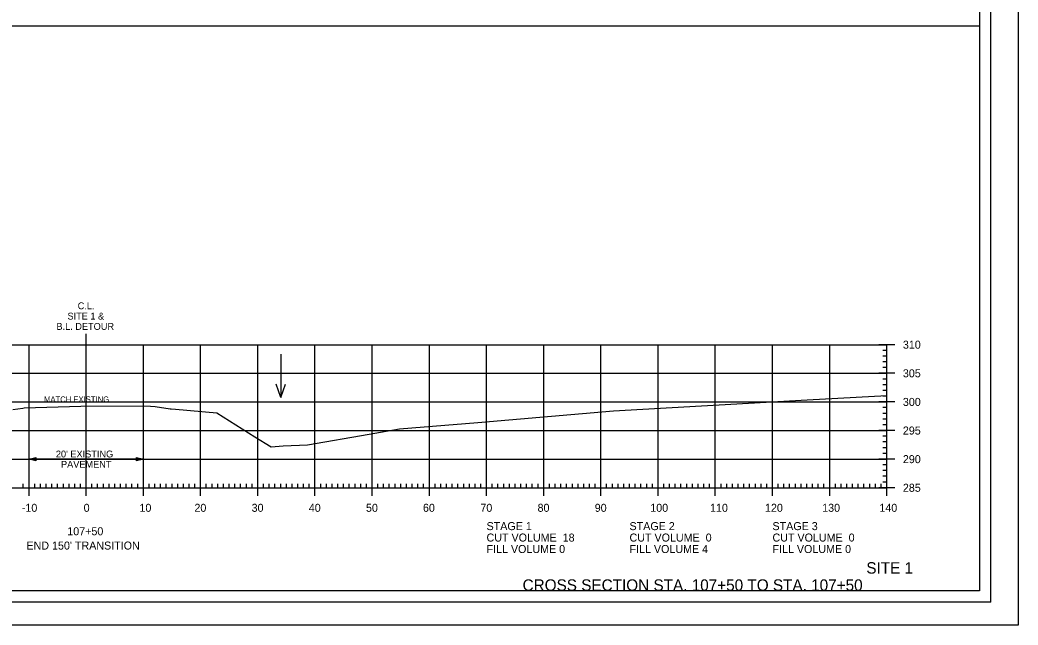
# Model space of a CAD drawing. Extents: x 1368713 to 1370673, y 380279 to 380950.
# Drawn here: x 1370140.7 to 1370315.2, y 380737.1 to 380842.8 of the extents above; entities that cross this region are included whole.
import ezdxf

# ---------------------------------------------------------------- set-up
doc = ezdxf.new("R2010")
doc.units = 0
for name, color, linetype in [('R_Axis', 7, 'Continuous'), ('R_Axis Annot', 7, 'Continuous'), ('R_Border', 7, 'Continuous'), ('R_Draft', 7, 'Continuous'), ('R_Exist Surface', 7, 'Continuous'), ('R_Grid', 7, 'Continuous'), ('R_No Plot', 7, 'Continuous'), ('R_ROW Annot', 7, 'Continuous'), ('R_Water Annot', 7, 'Continuous'), ('R_Xsect Slope', 7, 'Continuous')]:
    doc.layers.add(name, color=color, linetype=linetype)

msp = doc.modelspace()

# ---------------------------------------------------------------- linework, layer by layer
at = {"layer": 'R_Axis'}
for p, q in [((1370293.68, 380786.09), (1370290.88, 380786.09)), ((1370292.28, 380785.09), (1370291.58, 380785.09)), ((1370292.28, 380761.09), (1370292.28, 380786.09)), ((1370292.28, 380784.09), (1370291.58, 380784.09)), ((1370292.28, 380783.09), (1370291.58, 380783.09)), ((1370293.68, 380781.09), (1370290.88, 380781.09)), ((1370292.28, 380782.09), (1370291.58, 380782.09)), ((1370292.28, 380780.09), (1370291.58, 380780.09)), ((1370292.28, 380779.09), (1370291.58, 380779.09)), ((1370292.28, 380778.09), (1370291.58, 380778.09)), ((1370293.68, 380776.09), (1370290.88, 380776.09)), ((1370292.28, 380777.09), (1370291.58, 380777.09)), ((1370292.28, 380775.09), (1370291.58, 380775.09)), ((1370292.28, 380774.09), (1370291.58, 380774.09)), ((1370292.28, 380773.09), (1370291.58, 380773.09)), ((1370293.68, 380771.09), (1370290.88, 380771.09)), ((1370292.28, 380772.09), (1370291.58, 380772.09)), ((1370292.28, 380770.09), (1370291.58, 380770.09)), ((1370292.28, 380769.09), (1370291.58, 380769.09)), ((1370292.28, 380768.09), (1370291.58, 380768.09)), ((1370292.28, 380767.09), (1370291.58, 380767.09)), ((1370293.68, 380766.09), (1370290.88, 380766.09)), ((1370292.28, 380765.09), (1370291.58, 380765.09)), ((1370292.28, 380764.09), (1370291.58, 380764.09)), ((1370141.28, 380761.09), (1370141.28, 380761.79)), ((1370142.28, 380759.69), (1370142.28, 380762.49)), ((1370143.28, 380761.09), (1370143.28, 380761.79)), ((1370144.28, 380761.09), (1370144.28, 380761.79)), ((1370145.28, 380761.09), (1370145.28, 380761.79)), ((1370146.28, 380761.09), (1370146.28, 380761.79)), ((1370147.28, 380761.09), (1370147.28, 380761.79)), ((1370148.28, 380761.09), (1370148.28, 380761.79)), ((1370149.28, 380761.09), (1370149.28, 380761.79)), ((1370150.28, 380761.09), (1370150.28, 380761.79)), ((1370151.28, 380761.09), (1370151.28, 380761.79)), ((1370152.28, 380759.69), (1370152.28, 380762.49)), ((1370153.28, 380761.09), (1370153.28, 380761.79)), ((1370154.28, 380761.09), (1370154.28, 380761.79)), ((1370155.28, 380761.09), (1370155.28, 380761.79)), ((1370156.28, 380761.09), (1370156.28, 380761.79)), ((1370157.28, 380761.09), (1370157.28, 380761.79)), ((1370158.28, 380761.09), (1370158.28, 380761.79)), ((1370159.28, 380761.09), (1370159.28, 380761.79)), ((1370160.28, 380761.09), (1370160.28, 380761.79)), ((1370161.28, 380761.09), (1370161.28, 380761.79)), ((1370162.28, 380759.69), (1370162.28, 380762.49)), ((1370163.28, 380761.09), (1370163.28, 380761.79)), ((1370164.28, 380761.09), (1370164.28, 380761.79)), ((1370165.28, 380761.09), (1370165.28, 380761.79)), ((1370166.28, 380761.09), (1370166.28, 380761.79)), ((1370167.28, 380761.09), (1370167.28, 380761.79)), ((1370168.28, 380761.09), (1370168.28, 380761.79)), ((1370169.28, 380761.09), (1370169.28, 380761.79)), ((1370170.28, 380761.09), (1370170.28, 380761.79)), ((1370171.28, 380761.09), (1370171.28, 380761.79)), ((1370172.28, 380759.69), (1370172.28, 380762.49)), ((1370173.28, 380761.09), (1370173.28, 380761.79)), ((1370174.28, 380761.09), (1370174.28, 380761.79)), ((1370175.28, 380761.09), (1370175.28, 380761.79)), ((1370176.28, 380761.09), (1370176.28, 380761.79)), ((1370177.28, 380761.09), (1370177.28, 380761.79)), ((1370178.28, 380761.09), (1370178.28, 380761.79)), ((1370179.28, 380761.09), (1370179.28, 380761.79)), ((1370180.28, 380761.09), (1370180.28, 380761.79)), ((1370181.28, 380761.09), (1370181.28, 380761.79)), ((1370182.28, 380759.69), (1370182.28, 380762.49)), ((1370183.28, 380761.09), (1370183.28, 380761.79)), ((1370184.28, 380761.09), (1370184.28, 380761.79)), ((1370185.28, 380761.09), (1370185.28, 380761.79)), ((1370186.28, 380761.09), (1370186.28, 380761.79)), ((1370187.28, 380761.09), (1370187.28, 380761.79)), ((1370188.28, 380761.09), (1370188.28, 380761.79)), ((1370189.28, 380761.09), (1370189.28, 380761.79)), ((1370190.28, 380761.09), (1370190.28, 380761.79)), ((1370191.28, 380761.09), (1370191.28, 380761.79)), ((1370192.28, 380759.69), (1370192.28, 380762.49)), ((1370193.28, 380761.09), (1370193.28, 380761.79)), ((1370194.28, 380761.09), (1370194.28, 380761.79)), ((1370195.28, 380761.09), (1370195.28, 380761.79)), ((1370196.28, 380761.09), (1370196.28, 380761.79)), ((1370197.28, 380761.09), (1370197.28, 380761.79)), ((1370198.28, 380761.09), (1370198.28, 380761.79)), ((1370199.28, 380761.09), (1370199.28, 380761.79)), ((1370200.28, 380761.09), (1370200.28, 380761.79)), ((1370201.28, 380761.09), (1370201.28, 380761.79)), ((1370202.28, 380759.69), (1370202.28, 380762.49)), ((1370203.28, 380761.09), (1370203.28, 380761.79)), ((1370204.28, 380761.09), (1370204.28, 380761.79)), ((1370205.28, 380761.09), (1370205.28, 380761.79)), ((1370206.28, 380761.09), (1370206.28, 380761.79)), ((1370207.28, 380761.09), (1370207.28, 380761.79)), ((1370208.28, 380761.09), (1370208.28, 380761.79)), ((1370209.28, 380761.09), (1370209.28, 380761.79)), ((1370210.28, 380761.09), (1370210.28, 380761.79)), ((1370211.28, 380761.09), (1370211.28, 380761.79)), ((1370212.28, 380759.69), (1370212.28, 380762.49)), ((1370213.28, 380761.09), (1370213.28, 380761.79)), ((1370214.28, 380761.09), (1370214.28, 380761.79)), ((1370215.28, 380761.09), (1370215.28, 380761.79)), ((1370216.28, 380761.09), (1370216.28, 380761.79)), ((1370217.28, 380761.09), (1370217.28, 380761.79)), ((1370218.28, 380761.09), (1370218.28, 380761.79)), ((1370219.28, 380761.09), (1370219.28, 380761.79)), ((1370220.28, 380761.09), (1370220.28, 380761.79)), ((1370221.28, 380761.09), (1370221.28, 380761.79)), ((1370222.28, 380759.69), (1370222.28, 380762.49)), ((1370223.28, 380761.09), (1370223.28, 380761.79)), ((1370224.28, 380761.09), (1370224.28, 380761.79)), ((1370225.28, 380761.09), (1370225.28, 380761.79)), ((1370226.28, 380761.09), (1370226.28, 380761.79)), ((1370227.28, 380761.09), (1370227.28, 380761.79)), ((1370228.28, 380761.09), (1370228.28, 380761.79)), ((1370229.28, 380761.09), (1370229.28, 380761.79)), ((1370230.28, 380761.09), (1370230.28, 380761.79)), ((1370231.28, 380761.09), (1370231.28, 380761.79)), ((1370232.28, 380759.69), (1370232.28, 380762.49)), ((1370233.28, 380761.09), (1370233.28, 380761.79)), ((1370234.28, 380761.09), (1370234.28, 380761.79)), ((1370235.28, 380761.09), (1370235.28, 380761.79)), ((1370236.28, 380761.09), (1370236.28, 380761.79)), ((1370237.28, 380761.09), (1370237.28, 380761.79)), ((1370238.28, 380761.09), (1370238.28, 380761.79)), ((1370239.28, 380761.09), (1370239.28, 380761.79)), ((1370240.28, 380761.09), (1370240.28, 380761.79)), ((1370241.28, 380761.09), (1370241.28, 380761.79)), ((1370242.28, 380759.69), (1370242.28, 380762.49)), ((1370243.28, 380761.09), (1370243.28, 380761.79)), ((1370244.28, 380761.09), (1370244.28, 380761.79)), ((1370245.28, 380761.09), (1370245.28, 380761.79)), ((1370246.28, 380761.09), (1370246.28, 380761.79)), ((1370247.28, 380761.09), (1370247.28, 380761.79)), ((1370248.28, 380761.09), (1370248.28, 380761.79)), ((1370249.28, 380761.09), (1370249.28, 380761.79)), ((1370250.28, 380761.09), (1370250.28, 380761.79)), ((1370251.28, 380761.09), (1370251.28, 380761.79)), ((1370252.28, 380759.69), (1370252.28, 380762.49)), ((1370253.28, 380761.09), (1370253.28, 380761.79)), ((1370254.28, 380761.09), (1370254.28, 380761.79)), ((1370255.28, 380761.09), (1370255.28, 380761.79)), ((1370256.28, 380761.09), (1370256.28, 380761.79)), ((1370257.28, 380761.09), (1370257.28, 380761.79)), ((1370258.28, 380761.09), (1370258.28, 380761.79)), ((1370259.28, 380761.09), (1370259.28, 380761.79)), ((1370260.28, 380761.09), (1370260.28, 380761.79)), ((1370261.28, 380761.09), (1370261.28, 380761.79)), ((1370262.28, 380759.69), (1370262.28, 380762.49)), ((1370263.28, 380761.09), (1370263.28, 380761.79)), ((1370264.28, 380761.09), (1370264.28, 380761.79)), ((1370265.28, 380761.09), (1370265.28, 380761.79)), ((1370266.28, 380761.09), (1370266.28, 380761.79)), ((1370267.28, 380761.09), (1370267.28, 380761.79)), ((1370268.28, 380761.09), (1370268.28, 380761.79)), ((1370269.28, 380761.09), (1370269.28, 380761.79)), ((1370270.28, 380761.09), (1370270.28, 380761.79)), ((1370271.28, 380761.09), (1370271.28, 380761.79)), ((1370272.28, 380759.69), (1370272.28, 380762.49)), ((1370273.28, 380761.09), (1370273.28, 380761.79)), ((1370274.28, 380761.09), (1370274.28, 380761.79)), ((1370275.28, 380761.09), (1370275.28, 380761.79)), ((1370276.28, 380761.09), (1370276.28, 380761.79)), ((1370277.28, 380761.09), (1370277.28, 380761.79)), ((1370278.28, 380761.09), (1370278.28, 380761.79)), ((1370279.28, 380761.09), (1370279.28, 380761.79)), ((1370280.28, 380761.09), (1370280.28, 380761.79)), ((1370281.28, 380761.09), (1370281.28, 380761.79)), ((1370282.28, 380759.69), (1370282.28, 380762.49)), ((1370283.28, 380761.09), (1370283.28, 380761.79)), ((1370284.28, 380761.09), (1370284.28, 380761.79)), ((1370285.28, 380761.09), (1370285.28, 380761.79)), ((1370286.28, 380761.09), (1370286.28, 380761.79)), ((1370287.28, 380761.09), (1370287.28, 380761.79)), ((1370288.28, 380761.09), (1370288.28, 380761.79)), ((1370289.28, 380761.09), (1370289.28, 380761.79)), ((1370290.28, 380761.09), (1370290.28, 380761.79)), ((1370291.28, 380761.09), (1370291.28, 380761.79)), ((1370292.28, 380763.09), (1370291.58, 380763.09)), ((1370292.28, 380762.09), (1370291.58, 380762.09)), ((1370292.28, 380759.69), (1370292.28, 380762.49)), ((1370012.28, 380761.09), (1370292.28, 380761.09)), ((1370293.68, 380761.09), (1370290.88, 380761.09))]:
    msp.add_line(p, q, dxfattribs=at)
at = {"layer": 'R_Border'}
for q in [(1370310.46, 380946.55), (1369994.28, 380741.09)]:
    msp.add_line((1370310.46, 380741.09), q, dxfattribs=at)
at = {"layer": 'R_Exist Surface'}
msp.add_lwpolyline([(1370139.43, 380774.78), (1370141.19, 380775.02), (1370141.42, 380775.05), (1370151.35, 380775.36), (1370152.31, 380775.39), (1370163.5, 380775.32), (1370164.32, 380775.31), (1370166.97, 380774.89), (1370167.16, 380774.86), (1370167.91, 380774.8), (1370175.14, 380774.17), (1370181.76, 380769.97), (1370184.6, 380768.23), (1370186.71, 380768.4), (1370190.95, 380768.59), (1370201.73, 380770.47), (1370207.03, 380771.4), (1370220.77, 380772.47), (1370244.47, 380774.56), (1370278.37, 380776.47), (1370292.28, 380777.21)], dxfattribs=at)
at = {"layer": 'R_Grid'}
for p, q in [((1370012.28, 380786.09), (1370292.28, 380786.09)), ((1370142.28, 380761.09), (1370142.28, 380786.09)), ((1370152.28, 380761.09), (1370152.28, 380786.09)), ((1370162.28, 380761.09), (1370162.28, 380786.09)), ((1370172.28, 380761.09), (1370172.28, 380786.09)), ((1370182.28, 380761.09), (1370182.28, 380786.09)), ((1370192.28, 380761.09), (1370192.28, 380786.09)), ((1370202.28, 380761.09), (1370202.28, 380786.09)), ((1370212.28, 380761.09), (1370212.28, 380786.09)), ((1370222.28, 380761.09), (1370222.28, 380786.09)), ((1370232.28, 380761.09), (1370232.28, 380786.09)), ((1370242.28, 380761.09), (1370242.28, 380786.09)), ((1370252.28, 380761.09), (1370252.28, 380786.09)), ((1370262.28, 380761.09), (1370262.28, 380786.09)), ((1370272.28, 380761.09), (1370272.28, 380786.09)), ((1370282.28, 380761.09), (1370282.28, 380786.09)), ((1370292.28, 380761.09), (1370292.28, 380786.09)), ((1370012.28, 380781.09), (1370292.28, 380781.09)), ((1370012.28, 380776.09), (1370292.28, 380776.09)), ((1370012.28, 380771.09), (1370292.28, 380771.09)), ((1370012.28, 380766.09), (1370292.28, 380766.09)), ((1370012.28, 380761.09), (1370292.28, 380761.09))]:
    msp.add_line(p, q, dxfattribs=at)
at = {"layer": 'R_No Plot'}
for points in [[(1369981.88, 380950.45), (1370315.22, 380950.45), (1370315.22, 380737.11), (1369981.88, 380737.11)], [(1369996.28, 380944.55), (1370245.82, 380944.55), (1370245.82, 380934.67), (1370263.36, 380934.67), (1370287.46, 380934.67), (1370287.46, 380912.34), (1370308.46, 380912.34), (1370308.46, 380743.09), (1369996.28, 380743.09)], [(1369996.28, 380841.82), (1370308.46, 380841.82), (1370308.46, 380743.09), (1369996.28, 380743.09)]]:
    msp.add_lwpolyline(points, close=True, dxfattribs=at)
at = {"layer": 'R_ROW Annot'}
for p, q in [((1370152.28, 380784.21), (1370152.28, 380787.98)), ((1370142.28, 380764.21), (1370142.28, 380767.98)), ((1370162.28, 380764.21), (1370162.28, 380767.98)), ((1370162.28, 380766.09), (1370142.28, 380766.09))]:
    msp.add_line(p, q, dxfattribs=at)
for points in [[(1370143.48, 380765.79), (1370142.28, 380766.09), (1370143.48, 380766.39)], [(1370161.08, 380766.39), (1370162.28, 380766.09), (1370161.08, 380765.79)]]:
    msp.add_lwpolyline(points, close=True, dxfattribs=at)
at = {"layer": 'R_Water Annot'}
for p, q in [((1370186.31, 380784.42), (1370186.31, 380776.88)), ((1370186.31, 380776.88), (1370185.47, 380779.19)), ((1370186.31, 380776.88), (1370187.15, 380779.19))]:
    msp.add_line(p, q, dxfattribs=at)

# ---------------------------------------------------------------- texts
at = {"layer": 'R_Axis Annot'}
for s, p in [('310', (1370295.08, 380785.39)), ('305', (1370295.08, 380780.39)), ('300', (1370295.08, 380775.39)), ('295', (1370295.08, 380770.39)), ('290', (1370295.08, 380765.39)), ('285', (1370295.08, 380760.39)), ('-10', (1370141.02, 380756.89)), ('0', (1370151.83, 380756.89)), ('10', (1370161.59, 380756.89)), ('20', (1370171.2, 380756.89)), ('30', (1370181.2, 380756.89)), ('40', (1370191.2, 380756.89)), ('50', (1370201.2, 380756.89)), ('60', (1370211.16, 380756.89)), ('70', (1370221.2, 380756.89)), ('80', (1370231.2, 380756.89)), ('90', (1370241.2, 380756.89)), ('100', (1370250.91, 380756.89)), ('110', (1370261.36, 380756.89)), ('120', (1370270.97, 380756.89)), ('130', (1370280.97, 380756.89)), ('140', (1370290.97, 380756.89)), ('STAGE 1', (1370222.28, 380753.69)), ('STAGE 2', (1370247.28, 380753.69)), ('STAGE 3', (1370272.28, 380753.69)), ('107+50', (1370148.97, 380752.79)), ('CUT VOLUME  18', (1370222.28, 380751.69)), ('CUT VOLUME  0', (1370247.28, 380751.69)), ('CUT VOLUME  0', (1370272.28, 380751.69)), ("END 150' TRANSITION", (1370141.83, 380750.29)), ('FILL VOLUME 0', (1370222.28, 380749.69)), ('FILL VOLUME 4', (1370247.28, 380749.69)), ('FILL VOLUME 0', (1370272.28, 380749.69))]:
    msp.add_text(s, height=1.4, dxfattribs=at).set_placement(p)
at = {"layer": 'R_Draft'}
for s, p in [('SITE 1', (1370288.69, 380746.09)), ('CROSS SECTION STA. 107+50 TO STA. 107+50', (1370228.58, 380743.09))]:
    msp.add_text(s, height=2, dxfattribs=at).set_placement(p)
at = {"layer": 'R_ROW Annot'}
for s, p in [('C.L.', (1370150.79, 380792.28)), ('SITE 1 &', (1370149, 380790.48)), ('B.L. DETOUR', (1370147.07, 380788.68)), ("20' EXISTING", (1370146.97, 380766.39)), ('PAVEMENT', (1370147.87, 380764.59))]:
    msp.add_text(s, height=1.2, dxfattribs=at).set_placement(p)
at = {"layer": 'R_Xsect Slope'}
msp.add_text('MATCH EXISTING', height=1, dxfattribs=at).set_placement((1370144.91, 380776.05))

doc.saveas('drawing.dxf')
